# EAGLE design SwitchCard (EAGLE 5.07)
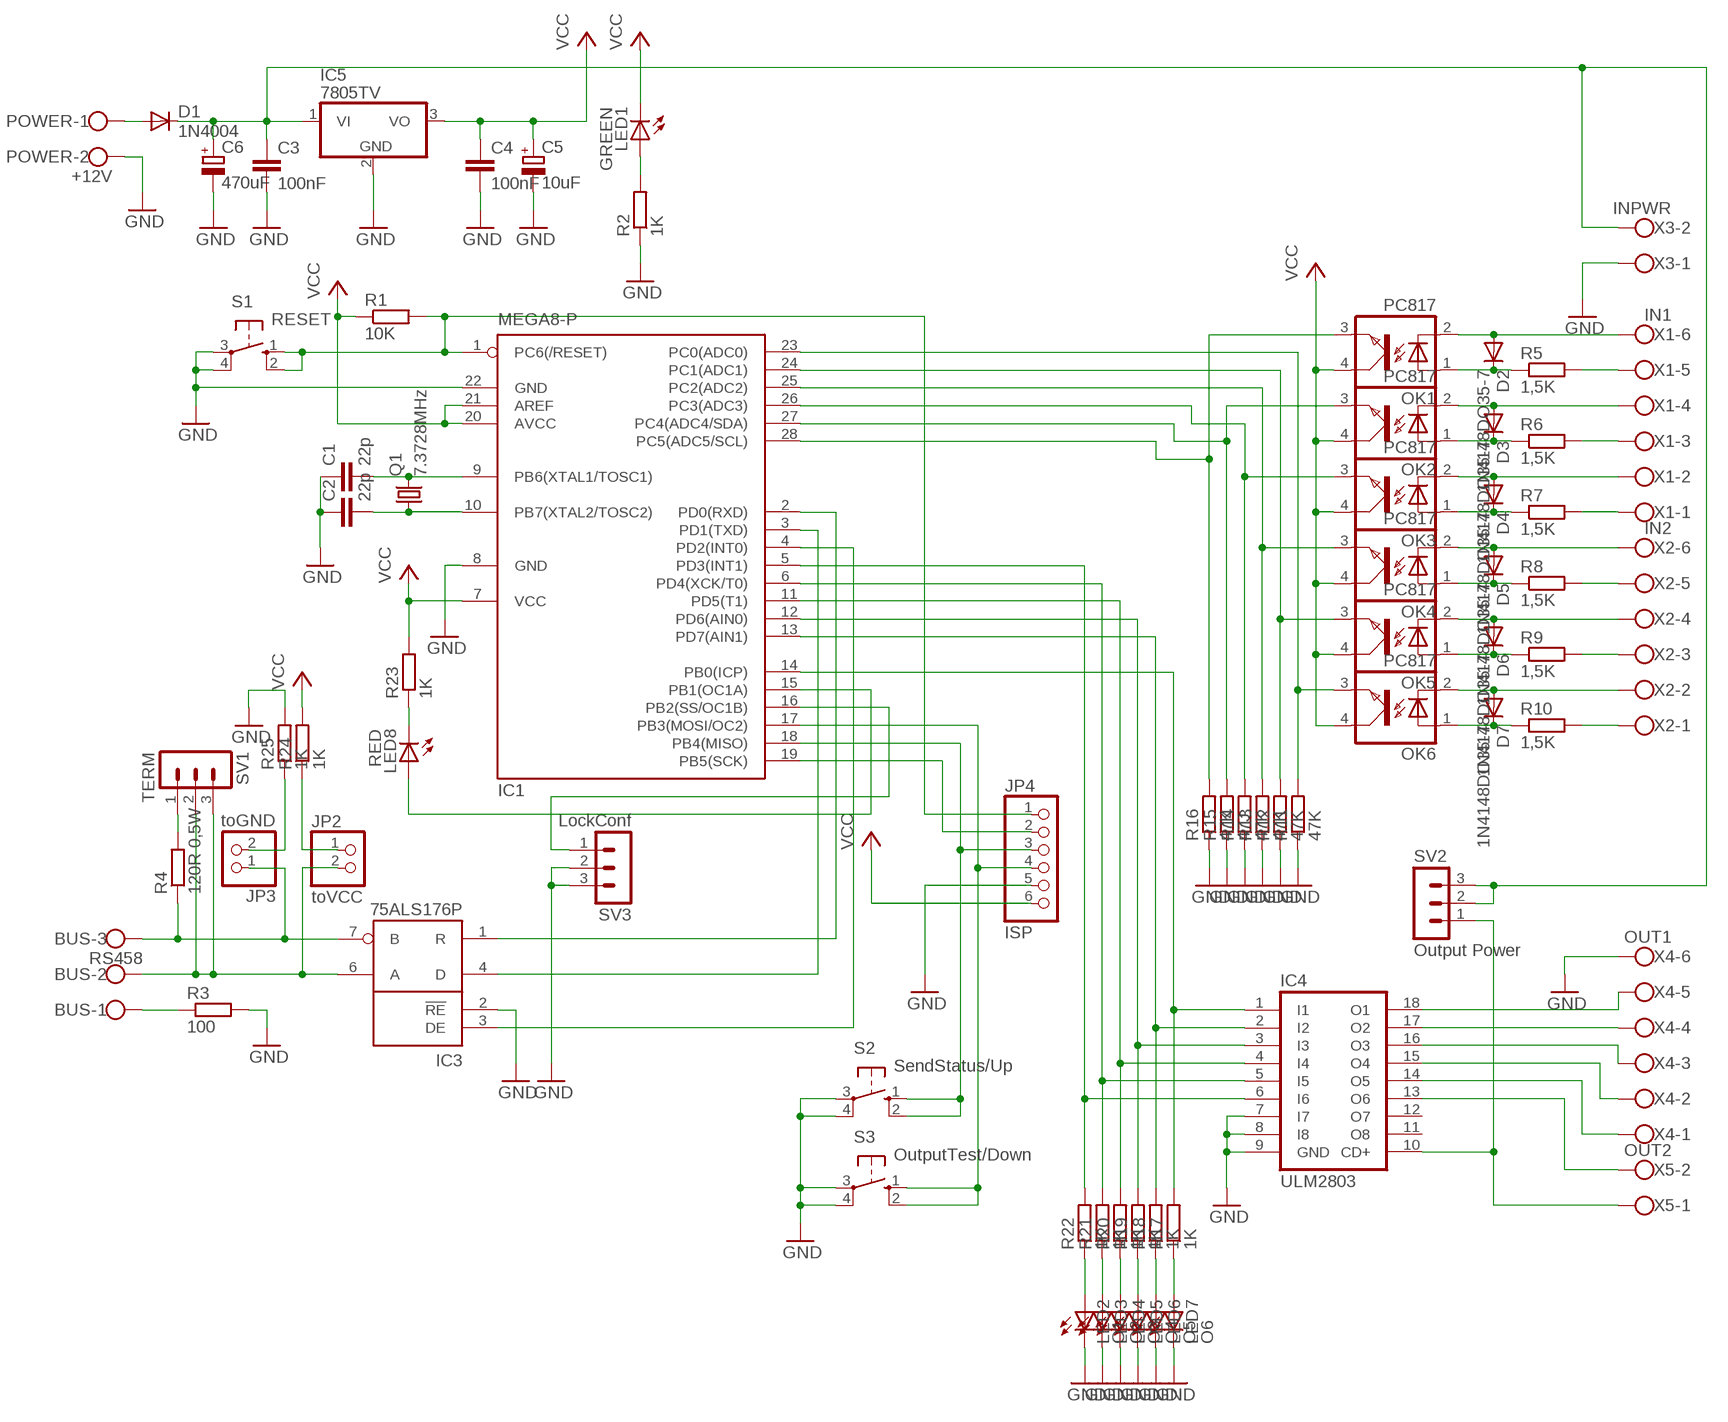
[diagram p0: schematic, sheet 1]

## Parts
BUS  RS458  W237-103  [W237-103]
C1  22p  C-EU025-025X050  [C025-025X050]
C2  22p  C-EU025-025X050  [C025-025X050]
C3  100nF  C-EU025-040X050  [C025-040X050]
C4  100nF  C-EU025-040X050  [C025-040X050]
C5  10uF  CPOL-EUE2-5  [E2-5]
C6  470uF  CPOL-EUE5-10.5  [E5-10,5]
D1  1N4004  [DO41-10]
D2  1N4148DO35-7  [DO35-7]
D3  1N4148DO35-7  [DO35-7]
D4  1N4148DO35-7  [DO35-7]
D5  1N4148DO35-7  [DO35-7]
D6  1N4148DO35-7  [DO35-7]
D7  1N4148DO35-7  [DO35-7]
IC1  MEGA8-P  [DIL28-3]
IC3  75ALS176P  [DIL08]
IC4  ULM2803  ULN2803A  [DIL18]
IC5  7805TV  [TO220V]
JP2  toVCC  PINHD-1X2  [1X02]
JP3  toGND  PINHD-1X2  [1X02]
JP4  ISP  PINHD-1X6  [1X06]
LED1  GREEN  LED3MM  [LED3MM]
LED2  O1  LED3MM  [LED3MM]
LED3  O2  LED3MM  [LED3MM]
LED4  O3  LED3MM  [LED3MM]
LED5  O4  LED3MM  [LED3MM]
LED6  O5  LED3MM  [LED3MM]
LED7  O6  LED3MM  [LED3MM]
LED8  RED  LED3MM  [LED3MM]
OK1  PC817  [DIL04]
OK2  PC817  [DIL04]
OK3  PC817  [DIL04]
OK4  PC817  [DIL04]
OK5  PC817  [DIL04]
OK6  PC817  [DIL04]
POWER  +12V  W237-102  [W237-102]
Q1  7.3728MHz  CRYSTALHC49S  [HC49/S]
R1  10K  R-EU_0204/7  [0204/7]
R2  1K  R-EU_0204/7  [0204/7]
R3  100  R-EU_0204/7  [0204/7]
R4  120R 0,5W  R-EU_0204/7  [0204/7]
R5  1,5K  R-EU_0204/7  [0204/7]
R6  1,5K  R-EU_0204/7  [0204/7]
R7  1,5K  R-EU_0204/7  [0204/7]
R8  1,5K  R-EU_0204/7  [0204/7]
R9  1,5K  R-EU_0204/7  [0204/7]
R10  1,5K  R-EU_0204/7  [0204/7]
R11  47K  R-EU_0204/7  [0204/7]
R12  47K  R-EU_0204/7  [0204/7]
R13  47K  R-EU_0204/7  [0204/7]
R14  47K  R-EU_0204/7  [0204/7]
R15  47J  R-EU_0204/7  [0204/7]
R16  47K  R-EU_0204/7  [0204/7]
R17  1K  R-EU_0204/7  [0204/7]
R18  1K  R-EU_0204/7  [0204/7]
R19  1K  R-EU_0204/7  [0204/7]
R20  1K  R-EU_0204/7  [0204/7]
R21  1K  R-EU_0204/7  [0204/7]
R22  1K  R-EU_0204/7  [0204/7]
R23  1K  R-EU_0204/7  [0204/7]
R24  1K  R-EU_0204/7  [0204/7]
R25  1K  R-EU_0204/7  [0204/7]
S1  RESET  10-XX  [B3F-10XX]
S2  SendStatus/Up  10-XX  [B3F-10XX]
S3  OutputTest/Down  10-XX  [B3F-10XX]
SV1  TERM  MA03-1  [MA03-1]
SV2  Output Power  MA03-1  [MA03-1]
SV3  LockConf  MA03-1  [MA03-1]
X1  IN1  W237-6  [W237-6]
X2  IN2  W237-6  [W237-6]
X3  INPWR  W237-102  [W237-102]
X4  OUT1  W237-136  [W237-136]
X5  OUT2  W237-102  [W237-102]

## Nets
GND: C1.1 C2.1 C3.2 C4.2 C5.- C6.- IC1.8(GND) IC1.22(GND) IC3.2(!RE) IC4.7(I7) IC4.8(I8) IC4.9(GND) IC5.2(GND) JP4.5 LED2.K(C) LED3.K(C) LED4.K(C) LED5.K(C) LED6.K(C) LED7.K(C) POWER.2 R2.1 R3.2 R11.1 R12.1 R13.1 R14.1 R15.1 R16.1 R25.2 S1.3(P) S1.4(P1) S2.3(P) S2.4(P1) S3.3(P) S3.4(P1) SV3.2 SV3.3 X3.1 X4.6
N$1: C1.2 IC1.9(PB6(XTAL1/TOSC1)) Q1.2
N$2: C2.2 IC1.10(PB7(XTAL2/TOSC2)) Q1.1
N$3: D1.A POWER.1
N$4: BUS.1 R3.1
N$5: C3.1 C6.+ D1.C IC5.1(VI) SV2.2 SV2.3 X3.2
N$6: LED1.A R2.2
N$8: IC1.3(PD1(TXD)) IC3.4(D)
N$9: BUS.3 IC3.7(B) JP3.1 R4.1
N$11: R4.2 SV1.1
N$12: IC1.2(PD0(RXD)) IC3.1(R)
N$13: IC1.4(PD2(INT0)) IC3.3(DE)
N$14: JP3.2 R25.1
N$15: IC1.19(PB5(SCK)) JP4.2
N$16: IC4.18(O1) X4.5
N$18: R10.2 X2.1
N$19: R9.2 X2.3
N$20: R8.2 X2.5
N$21: R7.2 X1.1
N$22: R6.2 X1.3
N$23: R5.2 X1.5
N$24: D2.A OK1.2(C) X1.6
N$25: D3.A OK2.2(C) X1.4
N$26: D4.A OK3.2(C) X1.2
N$27: D5.A OK4.2(C) X2.6
N$28: D6.A OK5.2(C) X2.4
N$29: D7.A OK6.2(C) X2.2
N$30: D7.C OK6.1(A) R10.1
N$31: D6.C OK5.1(A) R9.1
N$32: D5.C OK4.1(A) R8.1
N$33: D4.C OK3.1(A) R7.1
N$34: D3.C OK2.1(A) R6.1
N$35: D2.C OK1.1(A) R5.1
N$36: IC4.17(O2) X4.4
N$37: IC1.23(PC0(ADC0)) OK6.3(EMIT) R11.2
N$38: IC1.24(PC1(ADC1)) OK5.3(EMIT) R12.2
N$39: IC1.25(PC2(ADC2)) OK4.3(EMIT) R13.2
N$40: IC1.26(PC3(ADC3)) OK3.3(EMIT) R14.2
N$41: IC1.27(PC4(ADC4/SDA)) OK2.3(EMIT) R15.2
N$42: IC1.28(PC5(ADC5/SCL)) OK1.3(EMIT) R16.2
N$43: IC4.16(O3) X4.3
N$44: LED7.A R17.1
N$45: LED6.A R18.1
N$46: LED5.A R19.1
N$47: LED4.A R20.1
N$48: IC1.14(PB0(ICP)) IC4.1(I1) R17.2
N$49: IC1.13(PD7(AIN1)) IC4.2(I2) R18.2
N$50: IC1.12(PD6(AIN0)) IC4.3(I3) R19.2
N$51: IC1.11(PD5(T1)) IC4.4(I4) R20.2
N$52: IC1.6(PD4(XCK/T0)) IC4.5(I5) R21.2
N$53: IC1.5(PD3(INT1)) IC4.6(I6) R22.2
N$54: LED3.A R21.1
N$55: LED2.A R22.1
N$56: IC4.15(O4) X4.2
N$57: IC4.14(O5) X4.1
N$58: IC4.13(O6) X5.2
N$59: LED8.K(C) R23.1
N$60: IC1.15(PB1(OC1A)) LED8.A
N$61: IC1.16(PB2(SS/OC1B)) SV3.1
N$62: BUS.2 IC3.6(A) JP2.2 SV1.2 SV1.3
N$63: IC1.18(PB4(MISO)) JP4.3 S2.1(S) S2.2(S1)
N$64: JP2.1 R24.1
N$65: IC1.1(PC6(/RESET)) JP4.1 R1.2 S1.1(S) S1.2(S1)
N$66: IC1.17(PB3(MOSI/OC2)) JP4.4 S3.1(S) S3.2(S1)
N$68: IC4.10(CD+) SV2.1 X5.1
VCC: C4.1 C5.+ IC1.7(VCC) IC1.20(AVCC) IC1.21(AREF) IC5.3(VO) JP4.6 LED1.K(C) OK1.4(COL) OK2.4(COL) OK3.4(COL) OK4.4(COL) OK5.4(COL) OK6.4(COL) R1.1 R23.2 R24.2
Unconnected: IC4.11(O8) IC4.12(O7)

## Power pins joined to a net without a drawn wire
GND: IC3.5(GND)
VCC: IC3.8(VCC)

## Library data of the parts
BUS = con-wago-500:W237-103: WAGO SCREW CLAMP
C1-C4 = resistor:C-EU: CAPACITOR, European symbol
C5 C6 = resistor:CPOL-EU: POLARIZED CAPACITOR, European symbol
D1 = diode:1N4004: DIODE
D2-D7 = diode:1N4148: DIODE
IC1 = atmel:MEGA8-P: MICROCONTROLLER 8 Kbytes FLASH, 1 kbytes SRAM, 512 bytes EEPROM, USART, 4-channel 10 bit ADC, 2-channel 8 bit ADC Pin compatible with Atmega48, ATMega88, ATMega168 Source: avr.lbr
IC3 = texas:75ALS176: DIFFERENTIAL BUS TRANSCEIVERS TIA/EIA-422-B, TIA/EIA-422-B + TIA/EIA-422-B TIA/EIA-422-B Operate at Data Rates up to 35 Mbaud Source: http://focus.ti.com/lit/ds/symlink/sn65als176.pdf
IC4 = uln-udn:ULN2803A: DRIVER ARRAY
IC5 = linear:78*: Positive VOLTAGE REGULATOR Source: http://cache.national.com/ds/LM/LM78L05.pdf http://www.fairchildsemi.com/ds/LM/LM7805.pdf
JP2 JP3 = pinhead:PINHD-1X2: PIN HEADER
JP4 = pinhead:PINHD-1X6: PIN HEADER
LED1-LED8 = led:LED: LED
OK1-OK6 = optocoupler:PC817: SHARP OPTO COUPLER
POWER X3 X5 = con-wago-500:W237-102: WAGO SCREW CLAMP
Q1 = crystal:CRYSTAL: CRYSTAL
R1-R25 = resistor:R-EU_: RESISTOR, European symbol
S1-S3 = switch-omron:10-XX: OMRON SWITCH
SV1-SV3 = con-lstb:MA03-1: PIN HEADER
X1 X2 = con-wago-500:W237-6: WAGO SCREW CLAMP
X4 = con-wago-500:W237-136: WAGO SCREW CLAMP

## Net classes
0 default: width 0.61 mm

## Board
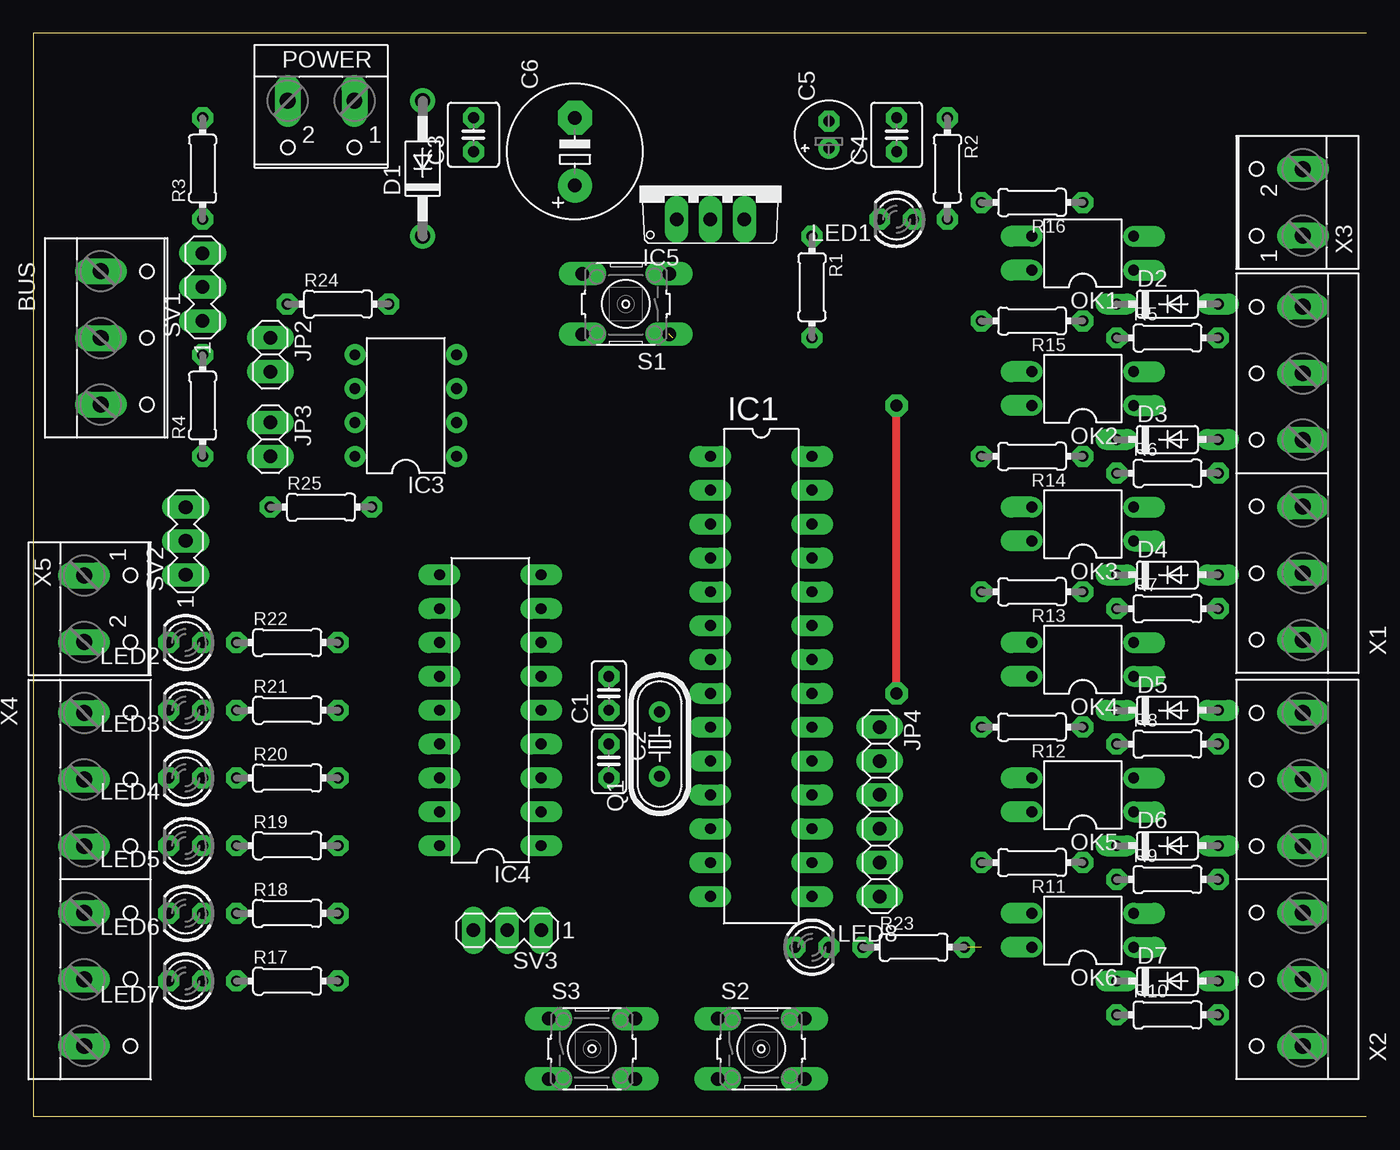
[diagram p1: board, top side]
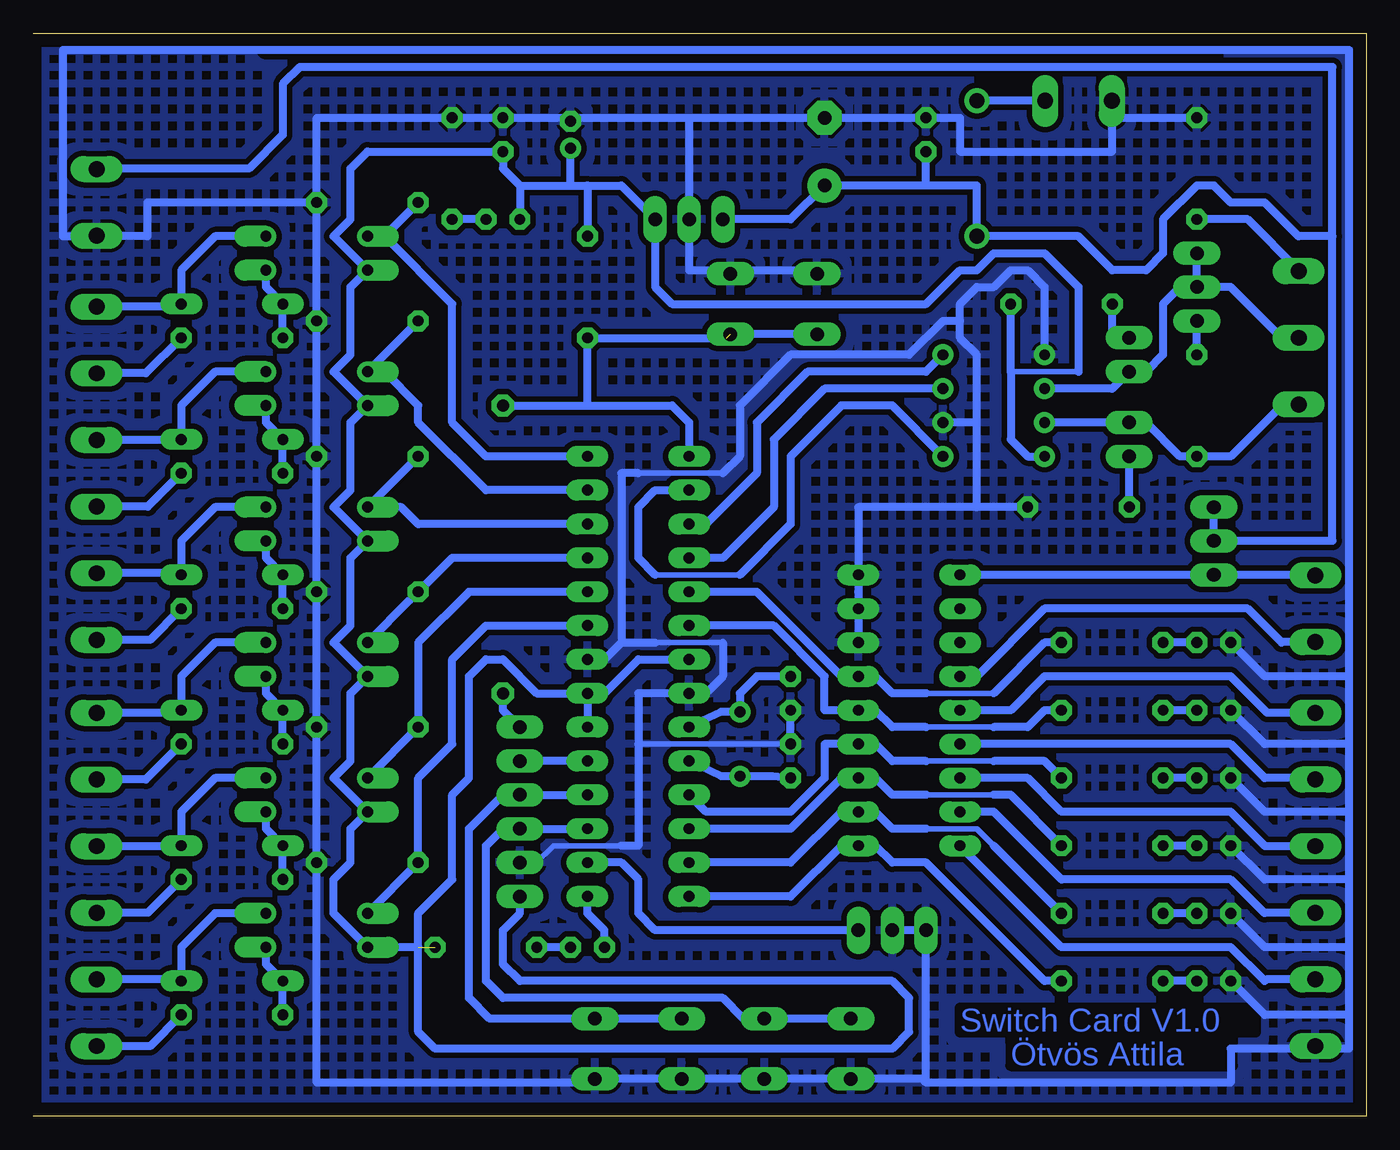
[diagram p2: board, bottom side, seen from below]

Size 100 x 81.27 mm. Coordinates in mm from the lower left corner, seen from the top.
Outline: 100,0 0,0 0,81.27 100,81.27
Copper layers (1*16): Top 0.035mm / dielectric 1.5mm / Bottom 0.035mm
Design rules "default *": minimum track width 8mil, minimum drill 24mil, track to track 8mil, track to pad 8mil, pad to pad 8mil, via to via 8mil, smd to smd 8mil, copper to edge 40mil, drill to drill 8mil, minimum pad ring 15mil, minimum via ring 15mil, stop-mask expansion 4mil, vias tented up to drill 0mil, thermal gap 10mil

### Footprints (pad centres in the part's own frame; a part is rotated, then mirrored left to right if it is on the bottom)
W237-103 = drill 1.194 long: 1 -5,-1.29; 2 0,-1.29; 3 5,-1.29
C025-025X050 = drill 0.813 octagon: 1 -1.27,0; 2 1.27,0
C025-040X050 = drill 0.813 octagon: 1 -1.27,0; 2 1.27,0
E2-5 = drill 0.813 pad 1.27 round: + -1.016,0 | drill 0.813 pad 1.27 octagon: - 1.016,0
E5-10,5 = drill 1.016 pad 2.54 round: + -2.54,0 | drill 1.016 pad 2.54 octagon: - 2.54,0
DO41-10 = drill 1.118 round: A 5.08,0; C -5.08,0
DO35-7 = drill 0.813 long: A 3.81,0; C -3.81,0
DIL28-3 = drill 0.813 long: 1 -16.51,-3.81; 2 -13.97,-3.81; 3 -11.43,-3.81; 4 -8.89,-3.81; 5 -6.35,-3.81; 6 -3.81,-3.81; 7 -1.27,-3.81; 8 1.27,-3.81; 9 3.81,-3.81; 10 6.35,-3.81; 11 8.89,-3.81; 12 11.43,-3.81; 13 13.97,-3.81; 14 16.51,-3.81; 15 16.51,3.81; 16 13.97,3.81; 17 11.43,3.81; 18 8.89,3.81; 19 6.35,3.81; 20 3.81,3.81; 21 1.27,3.81; 22 -1.27,3.81; 23 -3.81,3.81; 24 -6.35,3.81; 25 -8.89,3.81; 26 -11.43,3.81; 27 -13.97,3.81; 28 -16.51,3.81
DIL08 = drill 0.813 pad 1.27 round: 1 -3.81,-3.81; 2 -1.27,-3.81; 3 1.27,-3.81; 4 3.81,-3.81; 5 3.81,3.81; 6 1.27,3.81; 7 -1.27,3.81; 8 -3.81,3.81
DIL18 = drill 0.813 long: 1 -10.16,-3.81; 2 -7.62,-3.81; 3 -5.08,-3.81; 4 -2.54,-3.81; 5 0,-3.81; 6 2.54,-3.81; 7 5.08,-3.81; 8 7.62,-3.81; 9 10.16,-3.81; 10 10.16,3.81; 11 7.62,3.81; 12 5.08,3.81; 13 2.54,3.81; 14 0,3.81; 15 -2.54,3.81; 16 -5.08,3.81; 17 -7.62,3.81; 18 -10.16,3.81
TO220V = drill 1.016 long: 1 -2.54,-2.54; 2 0,-2.54; 3 2.54,-2.54
1X02 = drill 1.016 long: 1 -1.27,0; 2 1.27,0
1X06 = drill 1.016 long: 1 -6.35,0; 2 -3.81,0; 3 -1.27,0; 4 1.27,0; 5 3.81,0; 6 6.35,0
LED3MM = drill 0.813 octagon: A -1.27,0; K 1.27,0
DIL04 = drill 0.813 offset: 1 -1.27,-3.81; 2 1.27,-3.81; 3 1.27,3.81; 4 -1.27,3.81
W237-102 = drill 1.194 long: 1 -2.5,-1.27; 2 2.5,-1.27
HC49/S = drill 0.813 round: 1 -2.413,0; 2 2.413,0
0204/7 = drill 0.813 octagon: 1 -3.81,0; 2 3.81,0
B3F-10XX = drill 1.016 long: 1 -3.251,2.261; 2 3.251,2.261; 3 -3.251,-2.261; 4 3.251,-2.261
MA03-1 = drill 1.016 long: 1 -2.54,0; 2 0,0; 3 2.54,0
W237-6 = drill 1.194 long: 1 -12.5,-1.27; 2 -7.5,-1.27; 3 -2.5,-1.27; 4 2.5,-1.27; 5 7.5,-1.27; 6 12.5,-1.27
W237-136 = drill 1.194 long: 1 -12.5,-1.27; 2 -7.5,-1.27; 3 -2.5,-1.27; 4 2.5,-1.27; 5 7.5,-1.27; 6 12.5,-1.27

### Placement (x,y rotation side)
BUS  6.35,58.42 270 top
C1  43.18,31.75 90 top
C2  43.18,26.67 270 top
C3  33.02,73.66 90 top
C4  64.77,73.66 90 top
C5  59.69,73.66 90 top
C6  40.64,72.39 90 top
D1  29.21,71.12 90 top
D2  85.09,60.96 0 top
D3  85.09,50.8 0 top
D4  85.09,40.64 0 top
D5  85.09,30.48 0 top
D6  85.09,20.32 0 top
D7  85.09,10.16 0 top
IC1  54.61,33.02 270 top
IC3  27.94,53.34 90 top
IC4  34.29,30.48 90 top
IC5  50.8,69.85 0 top
JP2  17.78,57.15 270 top
JP3  17.78,50.8 270 top
JP4  63.5,22.86 270 top
LED1  64.77,67.31 180 top
LED2  11.43,35.56 180 top
LED3  11.43,30.48 180 top
LED4  11.43,25.4 180 top
LED5  11.43,20.32 180 top
LED6  11.43,15.24 180 top
LED7  11.43,10.16 180 top
LED8  58.42,12.7 0 top
OK1  78.74,64.77 90 top
OK2  78.74,54.61 90 top
OK3  78.74,44.45 90 top
OK4  78.74,34.29 90 top
OK5  78.74,24.13 90 top
OK6  78.74,13.97 90 top
POWER  21.59,74.93 180 top
Q1  46.99,27.94 90 top
R1  58.42,62.23 270 top
R2  68.58,71.12 270 top
R3  12.7,71.12 90 top
R4  12.7,53.34 90 top
R5  85.09,58.42 0 top
R6  85.09,48.26 0 top
R7  85.09,38.1 0 top
R8  85.09,27.94 0 top
R9  85.09,17.78 0 top
R10  85.09,7.62 0 top
R11  74.93,19.05 180 top
R12  74.93,29.21 180 top
R13  74.93,39.37 180 top
R14  74.93,49.53 180 top
R15  74.93,59.69 180 top
R16  74.93,68.58 180 top
R17  19.05,10.16 0 top
R18  19.05,15.24 0 top
R19  19.05,20.32 0 top
R20  19.05,25.4 0 top
R21  19.05,30.48 0 top
R22  19.05,35.56 0 top
R23  66.04,12.7 0 top
R24  22.86,60.96 0 top
R25  21.59,45.72 0 top
S1  44.45,60.96 180 top
S2  54.61,5.08 0 top
S3  41.91,5.08 0 top
SV1  12.7,62.23 90 top
SV2  11.43,43.18 90 top
SV3  35.56,13.97 180 top
X1  93.98,48.26 90 top
X2  93.98,17.78 90 top
X3  93.98,68.58 90 top
X4  5.08,17.78 270 top
X5  5.08,38.1 270 top

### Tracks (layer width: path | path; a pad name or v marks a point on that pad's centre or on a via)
GND
  Bottom 0.406: 19.09,74.89 19.09,74.93 | 95.21,66.04 X3.1 | 47.98,63.5 48.26,63.5 | IC4.7 IC4.8 38.1,39.37 | 53.34,35.56 48.26,35.56 | 48.26,48.26 54.61,48.26 | 62.23,19.05 60.96,20.32 55.88,20.32 | 54.61,27.94 C2.1
  Bottom 0.61: R16.1 R15.1 R14.1 R13.1 R12.1 R11.1 78.74,2.54 58.42,2.54 | POWER.2 19.09,74.93 R3.2 | 50.8,74.93 C6.- C3.2 30.48,74.93 30.48,72.39 19.05,72.39 19.05,74.89 19.09,74.89 | R16.1 91.44,68.58 91.44,66.04 95.21,66.04 | 1.27,17.78 1.27,22.86 | 1.27,22.86 1.27,27.94 | 1.27,27.94 1.27,33.02 | LED7.K 7.62,7.62 1.27,7.62 | LED6.K 7.62,12.7 1.27,12.7 | LED5.K 7.62,17.78 1.27,17.78 | LED4.K 7.62,22.86 1.27,22.86 | LED3.K 7.62,27.94 1.27,27.94 | LED2.K 7.62,33.02 1.27,33.02 | 29.21,52.07 IC3.2 | R25.2 29.21,45.72 | C2.1 C1.1 | 48.26,35.56 48.26,33.02 49.53,31.75 IC1.8 54.61,31.75 54.61,27.94 54.61,20.32 55.88,20.32 | IC4.7 38.1,39.37 IC4.9 38.1,45.72 29.21,45.72 | 48.26,48.26 46.99,49.53 46.99,53.34 43.18,57.15 34.29,57.15 31.75,59.69 30.48,59.69 | 30.48,59.69 30.48,60.96 29.21,62.23 27.94,62.23 26.67,63.5 25.4,63.5 24.13,62.23 IC3.5 | 30.48,59.69 30.48,58.42 29.21,57.15 29.21,52.07 | 29.21,45.72 29.21,52.07 | 1.27,7.62 1.27,12.7 | 1.27,12.7 1.27,17.78 | 62.23,19.05 JP4.5 | 55.88,35.56 57.15,34.29 IC1.22 | 55.88,35.56 53.34,35.56 | 1.27,7.62 1.27,5.08 10.16,5.08 10.16,2.54 33.02,2.54 | 33.02,2.54 33.3,2.82 S3.3 S3.4 S2.3 S2.4 | 1.27,33.02 1.27,80.01 97.79,80.01 97.79,66.04 95.25,66.04 | 50.8,74.93 IC5.2 50.8,63.5 47.98,63.5 41.2,63.5 S1.4 | R16.1 78.74,74.93 R2.1 C4.2 59.69,74.93 | 55.88,35.56 55.88,48.26 54.61,48.26 | 59.69,74.93 50.8,74.93 | 59.69,74.93 C5.- | SV3.2 SV3.3 33.02,2.54
  pour Bottom (isolate 0.406, hatched): 99.06,1.27 99.06,81.28 0,81.28 0,0 99.06,0
N$1
  Bottom 0.61: IC1.9 48.39,30.35 Q1.2 46.99,31.75 45.72,33.02 C1.2
N$2
  Bottom 0.61: IC1.10 48.39,25.53 Q1.1 44.58,25.53 C2.2
N$3
  Bottom 0.61: POWER.1 D1.A
N$4
  Bottom 0.406: BUS.1 5.06,63.48
  Bottom 0.61: 5.06,63.48 8.89,67.31 R3.1
N$5
  Bottom 0.406: 95.25,71.12 X3.2
  Bottom 0.61: 33.02,69.85 C3.1 | 33.02,69.85 C6.+ 43.18,67.31 IC5.1 | 95.25,71.12 83.82,71.12 81.28,73.66 81.28,77.47 80.01,78.74 2.54,78.74 2.54,66.04 | 33.02,69.85 29.21,69.85 D1.C 21.59,66.04 19.05,63.5 16.51,63.5 15.24,64.77 15.24,67.31 12.7,69.85 11.43,69.85 10.16,68.58 7.62,68.58 5.08,66.04 2.54,66.04 | SV2.3 SV2.2 2.54,43.18 2.54,66.04
N$6
  Bottom 0.61: LED1.A R2.2
N$8
  Bottom 0.61: IC1.3 49.53,44.45 45.72,48.26 45.72,52.07 41.91,55.88 33.02,55.88 IC3.4
N$9
  Bottom 0.61: BUS.3 6.27,53.42 10.16,49.53 R4.1 13.97,49.53 16.51,52.07 JP3.1 IC3.7
N$11
  Bottom 0.61: R4.2 SV1.1
N$12
  Bottom 0.406: 46.99,40.64 53.34,40.64
  Bottom 0.61: IC1.2 53.34,46.99 54.61,45.72 54.61,41.91 53.34,40.64 | 46.99,40.64 43.18,44.45 43.18,49.53 39.37,53.34 35.56,53.34 IC3.1
N$13
  Bottom 0.61: IC1.4 48.26,41.91 44.45,45.72 44.45,50.8 40.64,54.61 IC3.3
N$14
  Bottom 0.61: R25.1 JP3.2
N$15
  Bottom 0.61: IC1.19 JP4.2
N$16
  Bottom 0.61: X4.5 7.5,10.28 7.62,10.16 10.16,12.7 22.86,12.7 IC4.18
N$17
  Bottom 0.61: 11.43,80.01 82.55,80.01
N$18
  Bottom 0.61: X2.1 91.24,5.28 R10.2
N$19
  Bottom 0.61: X2.3 91.4,15.28 R9.2
N$20
  Bottom 0.61: X2.5 91.56,25.28 R8.2
N$21
  Bottom 0.61: X1.1 91.24,35.76 R7.2
N$22
  Bottom 0.61: X1.3 91.4,45.76 R6.2
N$23
  Bottom 0.61: X1.5 91.56,55.76 R5.2
N$24
  Bottom 0.406: D2.A 89.1,60.76
  Bottom 0.61: 89.1,60.76 X1.6 | OK1.2 86.36,66.04 88.9,63.5 D2.A
N$25
  Bottom 0.406: D3.A 88.94,50.76
  Bottom 0.61: 88.94,50.76 X1.4 | OK2.2 86.36,55.88 88.9,53.34 D3.A
N$26
  Bottom 0.406: D4.A 89.02,40.76
  Bottom 0.61: 89.02,40.76 X1.2 | OK3.2 86.36,45.72 88.9,43.18 D4.A
N$27
  Bottom 0.406: 87.63,30.48 87.83,30.28
  Bottom 0.61: 87.83,30.28 X2.6 | 87.63,30.48 D5.A 88.9,33.02 86.36,35.56 OK4.2
N$28
  Bottom 0.406: D6.A 88.94,20.28
  Bottom 0.61: 88.94,20.28 X2.4 | OK5.2 86.36,25.4 88.9,22.86 D6.A
N$29
  Bottom 0.406: D7.A 89.02,10.28
  Bottom 0.61: 89.02,10.28 X2.2 | OK6.2 86.36,15.24 88.9,12.7 D7.A
N$30
  Bottom 0.61: R10.1 D7.C 82.55,11.43 OK6.1
N$31
  Bottom 0.61: R9.1 D6.C 82.55,21.59 OK5.1
N$32
  Bottom 0.61: OK4.1 82.55,31.75 D5.C R8.1
N$33
  Bottom 0.61: OK3.1 82.55,41.91 D4.C R7.1
N$34
  Bottom 0.61: OK2.1 82.55,52.07 D3.C R6.1
N$35
  Bottom 0.61: OK1.1 82.55,62.23 D2.C R5.1
N$36
  Bottom 0.61: X4.4 7.58,15.28 7.62,15.24 10.16,17.78 22.86,17.78 27.94,22.86 IC4.17
N$37
  Bottom 0.61: OK6.3 R11.2 71.12,25.4 68.58,27.94 68.58,34.29 66.04,36.83 IC1.23
N$38
  Bottom 0.61: OK5.3 R12.2 71.12,35.56 67.31,39.37 IC1.24
N$39
  Bottom 0.406: R13.2 71.75,38.74
  Bottom 0.61: 71.75,38.74 OK4.3 | IC1.25 68.58,41.91 R13.2
N$40
  Bottom 0.61: R14.2 OK3.3 72.39,45.72 71.12,44.45 IC1.26
N$41
  Bottom 0.61: R15.2 OK2.3 73.66,55.88 71.12,53.34 71.12,52.07 66.04,46.99 IC1.27
N$42
  Bottom 0.61: 73.66,66.04 OK1.3 | 73.66,66.04 R16.2 | IC1.28 66.04,49.53 68.58,52.07 68.58,60.96 73.66,66.04
N$43
  Bottom 0.61: X4.3 7.58,20.28 10.16,22.86 22.86,22.86 25.4,25.4 IC4.16
N$44
  Bottom 0.61: LED7.A R17.1
N$45
  Bottom 0.61: LED6.A R18.1
N$46
  Bottom 0.61: LED5.A R19.1
N$47
  Bottom 0.61: LED4.A R20.1
N$48
  Bottom 0.61: IC1.14 43.18,16.51 39.37,20.32 IC4.1 36.83,20.32 35.56,19.05 33.02,19.05 24.13,10.16 R17.2
N$49
  Bottom 0.406: 27.94,20.32 29.21,21.59 33.02,21.59
  Bottom 0.61: IC1.13 43.18,19.05 39.37,22.86 IC4.2 36.83,22.86 35.56,21.59 33.02,21.59 | R18.2 27.94,20.32
N$50
  Bottom 0.406: 27.94,24.13 33.02,24.13
  Bottom 0.61: IC1.12 43.18,21.59 39.37,25.4 IC4.3 36.83,25.4 35.56,24.13 33.02,24.13 | R19.2 26.67,24.13 27.94,24.13
N$51
  Bottom 0.406: 27.94,26.67 33.02,26.67
  Bottom 0.61: IC1.11 49.53,22.86 43.18,22.86 40.64,25.4 40.64,27.94 IC4.4 36.83,27.94 35.56,26.67 33.02,26.67 | R20.2 24.13,26.67 27.94,26.67
N$52
  Bottom 0.406: 27.94,29.21 33.02,29.21
  Bottom 0.61: IC1.6 44.45,36.83 40.64,33.02 40.64,30.48 IC4.5 36.83,30.48 35.56,29.21 33.02,29.21 | R21.2 24.13,30.48 25.4,29.21 27.94,29.21
N$53
  Bottom 0.406: 27.94,31.75 33.02,31.75
  Bottom 0.61: IC1.5 45.72,39.37 39.37,33.02 IC4.6 36.83,33.02 35.56,31.75 33.02,31.75 | R22.2 24.13,35.56 27.94,31.75
N$54
  Bottom 0.61: LED3.A R21.1
N$55
  Bottom 0.61: LED2.A R22.1
N$56
  Bottom 0.406: X4.2 5.2,25.4
  Bottom 0.61: 5.2,25.4 7.62,25.4 10.16,27.94 IC4.15
N$57
  Bottom 0.61: X4.1 7.42,30.28 10.16,33.02 24.13,33.02 26.67,30.48 IC4.14
N$58
  Bottom 0.61: X5.2 6.31,35.6 6.35,35.56 8.89,38.1 24.13,38.1 29.21,33.02 IC4.13
N$59
  Bottom 0.61: LED8.K R23.1
N$60
  Bottom 0.61: IC1.15 58.42,15.24 57.15,13.97 LED8.A
N$61
  Bottom 0.61: IC1.16 55.88,19.05 54.61,17.78 54.61,15.24 53.34,13.97 SV3.1
N$62
  Bottom 0.61: BUS.2 6.35,58.42 10.16,62.23 SV1.2 | SV1.2 SV1.3 | IC3.6 19.05,54.61 JP2.2 16.51,55.88 15.24,57.15 15.24,60.96 13.97,62.23 SV1.2
N$63
  Bottom 0.61: IC1.18 JP4.3 64.77,24.13 67.31,21.59 67.31,8.89 65.76,7.34 S2.2 S2.1
N$64
  Bottom 0.61: R24.1 19.05,58.42 JP2.1
N$65  (via drill 0.9)  (1 unrouted)
  Top 0.61: v64.77,31.75 v64.77,53.34
  Bottom 0.61: v64.77,31.75 64.77,30.48 JP4.1 | v64.77,53.34 58.42,53.34 | 58.42,53.34 52.07,53.34 50.8,52.07 IC1.1 | 58.42,53.34 R1.2 47.98,58.42 | S1.2 S1.1
N$66
  Bottom 0.61: IC1.17 JP4.4 64.77,21.59 66.04,20.32 66.04,10.16 64.77,8.89 48.26,8.89 46.71,7.34 S3.2 S3.1
N$68
  Bottom 0.61: X5.1 3.81,40.64 SV2.1 IC4.10
VCC  (1 unrouted)
  Bottom 0.406: 21.59,55.88 26.67,55.88
  Bottom 0.61: 63.5,69.85 64.77,71.12 C4.1 74.93,72.39 76.2,71.12 76.2,67.31 77.47,66.04 OK1.4 76.2,62.23 76.2,57.15 77.47,55.88 OK2.4 76.2,52.07 76.2,46.99 77.47,45.72 OK3.4 76.2,41.91 76.2,36.83 77.47,35.56 OK4.4 76.2,31.75 76.2,26.67 77.47,25.4 OK5.4 76.2,21.59 76.2,19.05 77.47,17.78 77.47,15.24 OK6.4 71.12,12.7 | 63.5,69.85 LED1.K | IC3.8 25.4,49.53 26.67,50.8 26.67,55.88 R24.2 | JP4.6 63.5,15.24 64.77,13.97 64.77,11.43 63.5,10.16 35.56,10.16 34.29,8.89 34.29,6.35 35.56,5.08 69.85,5.08 71.12,6.35 71.12,12.7 | IC1.7 54.61,34.29 57.15,31.75 IC1.21 | 71.12,12.7 71.12,15.24 68.58,17.78 68.58,24.13 67.31,25.4 67.31,33.02 66.04,34.29 64.77,34.29 62.23,31.75 IC1.21 | 21.59,55.88 21.59,62.23 24.13,64.77 27.94,64.77 29.21,63.5 30.48,63.5 33.02,60.96 52.07,60.96 53.34,62.23 IC5.3 55.88,69.85 58.42,69.85 | IC1.21 IC1.20 | 63.5,69.85 59.69,69.85 | 59.69,69.85 58.42,69.85 | 58.42,69.85 R1.1 | 59.69,69.85 C5.+

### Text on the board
Bottom: Switch Card V1.0 | Ötvös Attila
